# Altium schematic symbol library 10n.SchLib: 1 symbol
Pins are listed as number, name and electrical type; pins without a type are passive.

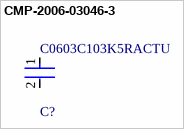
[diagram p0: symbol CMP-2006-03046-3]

## CMP-2006-03046-3
designator C?, comment C0603C103K5RACTU
CAP CER 10000PF 50V X7R 0603; Manufacturer: KEMET; Temperature Coefficient: 30ppm/°C; Capacitance: 10,000 pF; Automotive Grade: Grade 1; Material: Ceramic; Value: 10,000 pF; Tolerance: 0.1
footprint FP-C0603C-CF-IPC_B
footprint FP-C0603C-CF-MFG
footprint FP-C0603C-CF-IPC_A
footprint FP-C0603C-CF-IPC_C
pins: 1, 2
